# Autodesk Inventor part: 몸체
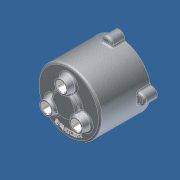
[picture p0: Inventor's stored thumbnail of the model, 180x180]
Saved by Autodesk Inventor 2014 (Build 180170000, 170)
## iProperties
Created: 2012-05
Part Number: 몸체
Document SubType Name: 모델링
Designer: SeoGD™
Material: 알루미늄 6061
Appearance: 알루미늄 - 평지
Density: 2.71 g/cm^3
Mass: 475.553 g
Surface Area: 687.661 cm^2
Volume: 175.481 cm^3
변환 표준: STEP AP214IS
파일 이름: C:\Users\SeoGD\Desktop\?쒗뿕\紐몄껜.stp
전처리기: Build: 253, Release: 2010 SP1 - Date: Wed 07/29/2009
전송 단위: 밀리미터
불확실성: 0.01
Author: SeoGD™
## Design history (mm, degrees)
sketch "스케치2"
  geometry: C1 r 50 at (0, 0); 1 further point
  constraints: 1 centre point, 1 coincident
  dimensions: "d9" = 100 diameter of C1
extrude "돌출2" new body sketch "스케치2" distance "d10" = 80; taper "d11" = 0 deg
feature "쉘1" dims "d12" = 5
sketch "스케치3" dims "d13" = 55
  geometry: C1 r 7.5 at (0, 27.5); C2 r 12.5 at (0, 27.5); 2 further points
  constraints: 2 centre point, 2 coincident, 2 vertical alignment, 2 other
  dimensions: "d14" = 15 diameter of C1; "d15" = 25 diameter of C2
extrude "돌출3" join sketch "스케치3" distance "d16" = 12; taper "d17" = -10 deg
hole "구멍2" diameter "d20" = 15; stored, may be unused: countersink angle "d24" = 90 deg, drill point angle "d26" = 118 deg; dims "d18" = 10, "d19" = 10, "d21" = 6, "d22" = 4, "d23" = 2, "d25" = 15
chamfer "모따기1" distance "d27" = 1; stored, may be unused: second distance "d28" = 2, angle "d29" = 45 deg
sketch "스케치4"
  geometry: L1 (0, 0)-(0, 88); L2 (0, 70)-(13.16, 70); L3 (-45, 75)-(45, 75) reference; L4 (-50, 80)-(50, 80) reference; L5 (13.16, 70)-(14.5, 75); L6 (20, 80)-(20, 88); L7 (20, 88)-(0, 88); L8 (20, 80)-(14.5, 75)
  constraints: 12 end point, 3 point on line, 2 perpendicular, 1 vertical
  dimensions: "d34" = 40 diameter of L6 L1; "d35" = 105 deg angle of L5 L3; "d36" = 5 distance between parallel lines of L2 L3; "d37" = 8 distance between parallel lines of L7 L4; "d51" = 29 diameter of L5.end L1
revolve "회전1" sketch "스케치4" stored, may be unused: angle "d38" = 90 deg
hole "구멍3" diameter "d41" = 15; stored, may be unused: countersink angle "d45" = 90 deg, drill point angle "d47" = 0 deg; dims "d39" = 10, "d40" = 10, "d42" = 6, "d43" = 22, "d44" = 13, "d46" = 15
chamfer "모따기2" distance "d48" = 1; stored, may be unused: second distance "d49" = 2, angle "d50" = 45 deg
fillet "모깎기1" dims "d52" = 3
fillet "모깎기2" dims "d53" = 3, "d72" = 0.2
sketch "스케치5"
  geometry: A1 r 50 centre (0, 0) between (50, 0) and (-8.074, 49.344) reference; A2 r 8.5 centre (0, 52) between (8.074, 49.344) and (-8.074, 49.344); 1 further point
  constraints: 5 point on circle, 1 centre point, 1 horizontal alignment
  dimensions: "d54" = 90 deg dimension on point (0, 0) A2.centre A1.start; "d55" = 52 distance of A2.centre point (0, 0); "d56" = 17 diameter of A2
extrude "돌출4" join sketch "스케치5" distance "d57" = 20; taper "d58" = 0 deg
fillet "모깎기3" dims "d59" = 3
hole "구멍4" diameter "d62" = 4.134; stored, may be unused: countersink angle "d66" = 90 deg, drill point angle "d68" = 118 deg; dims "d60" = 10, "d61" = 10, "d63" = 12, "d64" = 22, "d65" = 13, "d67" = 15
sketch "스케치6"
  geometry: C1 r 47 at (0, 0) reference; C2 r 42.5 at (0, 0); 1 further point
  constraints: 1 centre point, 1 coincident, 1 other
  dimensions: "d73" = 85 diameter of C2
feature "엠보싱1" sketch "스케치6" dims "d74" = 1, "d75" = 0
node "솔리드1"
node "솔리드 본체"
node "곡면 본체"
pattern_circular "원형 패턴1" dims "d31" = 360 deg
pattern_circular "원형 패턴2" dims "d70" = 360 deg
node "솔리드2"
